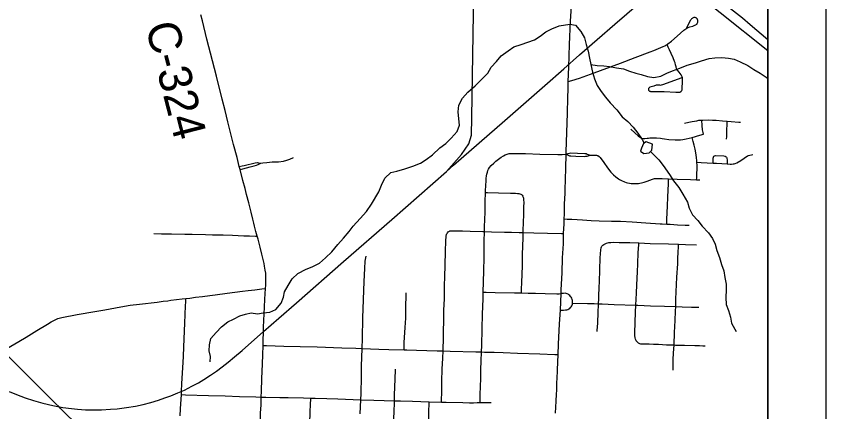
# Model space of a CAD drawing. Extents: x 0 to 34, y 0 to 22.
# Drawn here: x 7.601 to 9, y 14.792 to 15.476 of the extents above; entities that cross this region are included whole.
import ezdxf

# ---------------------------------------------------------------- set-up
doc = ezdxf.new("R2010")
doc.units = 0
for name, color, linetype in [('GM_X_City_Street', 7, 'Continuous'), ('GM_X_Corporation', 7, 'Continuous'), ('GM_X_County_Road', 7, 'Continuous'), ('GM_X_County_Road_Text', 7, 'Continuous'), ('GM_X_Minor_Lake', 7, 'Continuous'), ('GM_X_Minor_River', 7, 'Continuous'), ('GM_X_Rail_Line', 7, 'Continuous'), ('GM_X_State_Route', 7, 'Continuous'), ('SH_Data', 7, 'Continuous')]:
    doc.layers.add(name, color=color, linetype=linetype)

msp = doc.modelspace()

# ---------------------------------------------------------------- linework, layer by layer
at = {"layer": 'GM_X_City_Street'}
for points in [[(8.5552, 15.3632), (8.5614, 15.365), (8.5747, 15.3691), (8.5934, 15.3756), (8.6455, 15.395), (8.6704, 15.4046), (8.6965, 15.4144), (8.7027, 15.4167), (8.7152, 15.4219), (8.7191, 15.4236), (8.7219, 15.425), (8.7239, 15.426), (8.7258, 15.4273), (8.7269, 15.4281), (8.7333, 15.433), (8.7432, 15.4415), (8.755, 15.4517), (8.7602, 15.4552), (8.7625, 15.4564), (8.765, 15.4573), (8.7701, 15.459), (8.7737, 15.4603), (8.7752, 15.461), (8.7762, 15.4617), (8.777, 15.4623), (8.7775, 15.463), (8.778, 15.4638), (8.7784, 15.4646), (8.7787, 15.4655), (8.779, 15.4667), (8.779, 15.468), (8.7789, 15.4689), (8.7786, 15.4698), (8.7781, 15.4709), (8.7774, 15.4719), (8.7767, 15.4727), (8.7761, 15.4731), (8.7754, 15.4734), (8.7744, 15.4737), (8.7732, 15.4738), (8.7718, 15.4737), (8.7708, 15.4733), (8.7698, 15.4728), (8.769, 15.4721), (8.768, 15.4714), (8.7672, 15.4704), (8.7662, 15.4689), (8.7624, 15.4616), (8.7595, 15.4555)], [(8.7511, 15.3695), (8.718, 15.3571), (8.7156, 15.3565), (8.7144, 15.3564), (8.7131, 15.3565), (8.71, 15.3569), (8.708, 15.3567), (8.7069, 15.3565), (8.7027, 15.3553), (8.6962, 15.3532), (8.6952, 15.3526), (8.6947, 15.3521), (8.6939, 15.3512), (8.6935, 15.35), (8.6935, 15.3494), (8.6938, 15.3481), (8.6943, 15.3473), (8.695, 15.3468), (8.6957, 15.3464), (8.6964, 15.3462), (8.6972, 15.3461), (8.6985, 15.346), (8.7205, 15.3457), (8.741, 15.3448), (8.747, 15.3446), (8.7484, 15.3447), (8.7498, 15.3456), (8.7504, 15.3461), (8.7509, 15.3468), (8.7513, 15.3477), (8.7517, 15.3492), (8.7519, 15.3508), (8.7527, 15.3632), (8.7527, 15.3675), (8.7525, 15.3692), (8.752, 15.3711), (8.7515, 15.3725), (8.7502, 15.3744), (8.7467, 15.3794), (8.744, 15.3828), (8.7429, 15.3844), (8.7423, 15.3858), (8.7414, 15.3886), (8.7405, 15.3921), (8.7397, 15.3951), (8.7386, 15.3978), (8.7362, 15.4039), (8.7328, 15.4117), (8.7301, 15.4178), (8.7279, 15.4227), (8.7258, 15.4273)], [(8.7558, 15.2913), (8.7634, 15.2927), (8.7692, 15.2938), (8.7771, 15.2954), (8.7804, 15.296), (8.7838, 15.2964), (8.7858, 15.2965), (8.7874, 15.2965), (8.7978, 15.2966), (8.8042, 15.2963), (8.8108, 15.296), (8.8216, 15.295), (8.8298, 15.2943), (8.8364, 15.2938), (8.8498, 15.2929), (8.8529, 15.2927)], [(8.7889, 15.2718), (8.7881, 15.2747), (8.7875, 15.2771), (8.7871, 15.2794), (8.7869, 15.2813), (8.7865, 15.2852), (8.7862, 15.2887), (8.7859, 15.2946), (8.7858, 15.2965)], [(8.8286, 15.2636), (8.8288, 15.2682), (8.829, 15.2734), (8.8291, 15.2801), (8.8296, 15.2881), (8.8297, 15.2919), (8.8298, 15.2943)], [(8.6633, 15.2809), (8.6701, 15.2743), (8.6759, 15.2691), (8.6783, 15.2672), (8.6799, 15.2661), (8.6817, 15.2652), (8.6834, 15.2646), (8.6847, 15.2644), (8.6862, 15.2644), (8.6876, 15.2644), (8.6916, 15.2649), (8.6937, 15.2652), (8.6962, 15.2656), (8.6993, 15.2658), (8.7029, 15.2659), (8.7075, 15.2657), (8.7142, 15.2652), (8.7173, 15.2648), (8.7214, 15.2643), (8.7288, 15.2629)], [(8.7288, 15.2629), (8.74, 15.2623), (8.7433, 15.2622), (8.7463, 15.2622), (8.7491, 15.2624), (8.753, 15.2627), (8.7588, 15.2639), (8.7691, 15.2666), (8.7824, 15.2701), (8.7889, 15.2718)], [(8.7769, 15.1931), (8.777, 15.1965), (8.7772, 15.2035), (8.7775, 15.2123), (8.7775, 15.2181), (8.7773, 15.2235), (8.7772, 15.2267), (8.7768, 15.2311), (8.7761, 15.2361), (8.7743, 15.2459), (8.7725, 15.2532), (8.771, 15.2593), (8.7691, 15.2666)], [(8.0239, 15.2218), (8.0275, 15.2224), (8.0343, 15.2234), (8.0436, 15.2241), (8.0547, 15.2245), (8.0632, 15.2256), (8.0692, 15.227), (8.0743, 15.2288), (8.0803, 15.2317)], [(8.422, 15.2181), (8.4263, 15.222), (8.4302, 15.2256), (8.4346, 15.2291), (8.4393, 15.2325), (8.443, 15.2347), (8.4462, 15.2362), (8.4498, 15.2376), (8.4532, 15.2384), (8.456, 15.2387), (8.4597, 15.2389), (8.4672, 15.2389), (8.4802, 15.2384), (8.4815, 15.2384), (8.5059, 15.2377), (8.5368, 15.237), (8.5447, 15.237), (8.5515, 15.2374)], [(8.5515, 15.2374), (8.5549, 15.2388), (8.557, 15.2394), (8.5593, 15.2396), (8.5712, 15.2393), (8.5838, 15.2387), (8.586, 15.2384), (8.588, 15.2378), (8.5932, 15.2359)], [(8.5515, 15.2374), (8.5549, 15.2357), (8.5573, 15.2349), (8.5595, 15.2344), (8.568, 15.234), (8.5824, 15.2336), (8.5851, 15.2339), (8.5875, 15.2343), (8.5932, 15.2359)], [(8.5932, 15.2359), (8.5988, 15.236), (8.6023, 15.2359), (8.604, 15.2357), (8.6052, 15.2354), (8.6063, 15.235), (8.6082, 15.2337), (8.6102, 15.2315), (8.6166, 15.2232), (8.6231, 15.2141), (8.6287, 15.2066), (8.633, 15.202), (8.6372, 15.1982), (8.6418, 15.1949), (8.6437, 15.1937), (8.6468, 15.1921), (8.652, 15.1899), (8.655, 15.1888), (8.6577, 15.1881), (8.6609, 15.1875), (8.6637, 15.1871), (8.6671, 15.1868), (8.67, 15.1867), (8.6733, 15.1867), (8.6762, 15.187), (8.6785, 15.1873), (8.6814, 15.1878), (8.6838, 15.1884), (8.6862, 15.1891), (8.6915, 15.191), (8.7006, 15.1945), (8.7024, 15.1951), (8.704, 15.1954), (8.7062, 15.1956), (8.7092, 15.1957), (8.7174, 15.1955), (8.7284, 15.1949), (8.7435, 15.1944), (8.7665, 15.1935), (8.7769, 15.1931), (8.7825, 15.1929)], [(8.7773, 15.2235), (8.7848, 15.2231), (8.8055, 15.2221), (8.8114, 15.2217), (8.8298, 15.2208), (8.8349, 15.2205), (8.8372, 15.2205), (8.8397, 15.2207), (8.8415, 15.221), (8.8432, 15.2215), (8.8465, 15.2228), (8.8533, 15.2268), (8.8647, 15.2344), (8.8664, 15.2352), (8.8685, 15.236), (8.8715, 15.2366), (8.8739, 15.2368)], [(8.8055, 15.2221), (8.8055, 15.2275), (8.8055, 15.2306), (8.8058, 15.2325), (8.8067, 15.2341), (8.8077, 15.2348), (8.8095, 15.2352), (8.8239, 15.2345), (8.8263, 15.2341), (8.8279, 15.2332), (8.8287, 15.2322), (8.8292, 15.2311), (8.8294, 15.2267), (8.8298, 15.2208)], [(7.9868, 15.2164), (7.9915, 15.2173), (7.9955, 15.2182), (8.0144, 15.2226), (8.0181, 15.223), (8.0201, 15.2226), (8.0239, 15.2218)], [(7.9882, 15.211), (7.993, 15.2122), (8.0056, 15.2155), (8.0125, 15.2172), (8.0167, 15.2183), (8.0196, 15.2194), (8.0239, 15.2218)], [(8.4027, 14.8081), (8.4028, 14.811), (8.4032, 14.8236), (8.4034, 14.835), (8.404, 14.8512), (8.4043, 14.8655), (8.4048, 14.8796), (8.4053, 14.8957), (8.4056, 14.907), (8.4063, 14.9359), (8.407, 14.9608), (8.4079, 14.9874), (8.4082, 14.9991), (8.409, 15.0351), (8.4098, 15.0598), (8.4099, 15.0864), (8.4103, 15.1036), (8.4106, 15.1131), (8.411, 15.1236), (8.4113, 15.1383), (8.4118, 15.1551), (8.4122, 15.1712), (8.4123, 15.1735), (8.4126, 15.1837), (8.413, 15.1906), (8.4134, 15.1954), (8.4139, 15.1999), (8.4145, 15.2029), (8.4153, 15.2063), (8.4163, 15.2095), (8.4173, 15.2114), (8.4189, 15.2144), (8.422, 15.2181)], [(8.7252, 15.1167), (8.7255, 15.1235), (8.7256, 15.1253), (8.7266, 15.1476), (8.7273, 15.1637), (8.7281, 15.186), (8.7284, 15.1949)], [(8.4122, 15.1712), (8.4157, 15.1712), (8.4346, 15.1705), (8.4552, 15.1701), (8.4641, 15.1699), (8.4672, 15.1698), (8.4696, 15.1696), (8.4714, 15.1692), (8.4731, 15.1684), (8.4741, 15.1676), (8.4755, 15.1664), (8.4765, 15.1649)], [(8.4744, 14.9978), (8.4746, 15.0042), (8.4749, 15.016), (8.4758, 15.0444), (8.4762, 15.0625), (8.4768, 15.0801), (8.477, 15.0913), (8.4773, 15.1023), (8.4774, 15.1057), (8.4782, 15.133), (8.4784, 15.1373), (8.4785, 15.1453), (8.4787, 15.1552), (8.4786, 15.1572), (8.4784, 15.1595), (8.4781, 15.161), (8.4776, 15.1625), (8.4765, 15.1649)], [(8.5482, 15.1255), (8.5532, 15.1253), (8.5614, 15.1251), (8.5797, 15.124), (8.5947, 15.123), (8.6084, 15.1225), (8.63, 15.1219), (8.6454, 15.1215), (8.6655, 15.1204), (8.6892, 15.1188), (8.7138, 15.1172), (8.7173, 15.1171), (8.7252, 15.1167), (8.7309, 15.1164), (8.7439, 15.1156), (8.7573, 15.115), (8.7638, 15.1147)], [(8.3478, 15.1032), (8.3489, 15.1041), (8.3499, 15.1046), (8.3508, 15.1049), (8.3533, 15.1051), (8.3584, 15.1052), (8.3725, 15.1048), (8.3857, 15.1043), (8.4073, 15.1036), (8.4103, 15.1036), (8.4226, 15.1033), (8.4449, 15.103), (8.4573, 15.1027), (8.4702, 15.1024), (8.4773, 15.1023), (8.4958, 15.1018), (8.519, 15.101), (8.5432, 15.1004), (8.5471, 15.1003)], [(7.8391, 15.1004), (7.8522, 15.1), (7.8695, 15.0997), (7.893, 15.0992), (7.8973, 15.0992), (7.9053, 15.0991), (7.9282, 15.0987), (7.9407, 15.0984), (7.9493, 15.0983), (7.9587, 15.098), (7.9752, 15.0974), (7.9948, 15.0966), (8.0046, 15.0963), (8.0147, 15.0961), (8.0178, 15.096)], [(8.336, 14.8091), (8.3366, 14.8295), (8.3368, 14.8451), (8.3373, 14.8658), (8.3383, 14.8852), (8.3388, 14.8975), (8.3391, 14.9023), (8.3394, 14.9168), (8.3397, 14.9322), (8.34, 14.9491), (8.3403, 14.959), (8.3404, 14.9677), (8.3411, 14.9877), (8.3413, 14.9973), (8.3415, 15.0108), (8.342, 15.0255), (8.3426, 15.0457), (8.3432, 15.0696), (8.3437, 15.0878), (8.3441, 15.0953), (8.3443, 15.0968), (8.3447, 15.0983), (8.345, 15.0993), (8.3457, 15.1004), (8.3466, 15.1016), (8.3478, 15.1032)], [(8.605, 14.931), (8.6052, 14.9329), (8.6059, 14.9452), (8.6066, 14.9645), (8.6072, 14.9771), (8.6073, 14.9789), (8.6077, 14.9878), (8.6079, 14.9921), (8.6087, 15.0075), (8.609, 15.0168), (8.6097, 15.0379), (8.6104, 15.0585), (8.6106, 15.0653), (8.6111, 15.0721), (8.612, 15.0757), (8.6126, 15.0773), (8.6133, 15.0784), (8.615, 15.0803), (8.6163, 15.0813), (8.6175, 15.0821), (8.6212, 15.0838)], [(8.6212, 15.0838), (8.6254, 15.0847), (8.6288, 15.0851), (8.6327, 15.0852), (8.6431, 15.0849), (8.6617, 15.0846), (8.6769, 15.0842), (8.6965, 15.0834), (8.7281, 15.0825), (8.7454, 15.0819), (8.7579, 15.0814), (8.7767, 15.0808)], [(8.6749, 14.9127), (8.6735, 14.9138), (8.6724, 14.9152), (8.6717, 14.9165), (8.6711, 14.9179), (8.6705, 14.9204), (8.6702, 14.9242), (8.67, 14.9289), (8.6715, 14.9643), (8.6721, 14.9764), (8.6731, 14.9972), (8.6738, 15.012), (8.6748, 15.0343), (8.6753, 15.0478), (8.6761, 15.0676), (8.6768, 15.0809), (8.6769, 15.0842)], [(8.7361, 14.864), (8.7365, 14.8829), (8.7371, 14.8934), (8.7378, 14.9078), (8.7389, 14.9294), (8.7398, 14.9501), (8.7405, 14.9662), (8.7407, 14.9741), (8.7409, 14.9768), (8.7412, 14.9868), (8.7429, 15.0248), (8.7441, 15.048), (8.7445, 15.0592), (8.7448, 15.0662), (8.7453, 15.079), (8.7454, 15.0819)], [(8.1959, 14.7887), (8.1964, 14.801), (8.1968, 14.8132), (8.1972, 14.8241), (8.1978, 14.8527), (8.1979, 14.8677), (8.1979, 14.8714), (8.1988, 14.9017), (8.1994, 14.9192), (8.2005, 14.9546), (8.2025, 15.0176), (8.2036, 15.0398), (8.2044, 15.0528), (8.2052, 15.0583), (8.2057, 15.0612)], [(7.5855, 14.9017), (7.6058, 14.9139), (7.6185, 14.9215), (7.637, 14.9327), (7.6555, 14.9439), (7.6617, 14.9476), (7.664, 14.949), (7.6689, 14.9515), (7.6736, 14.9534), (7.6805, 14.9552), (7.7069, 14.9602), (7.737, 14.9654), (7.7548, 14.9685), (7.7819, 14.9737), (7.7984, 14.9765), (7.8142, 14.9783), (7.8448, 14.982), (7.8553, 14.9834), (7.8633, 14.9843), (7.8688, 14.985), (7.888, 14.9873), (7.8944, 14.9881), (7.9012, 14.9889), (7.9114, 14.9902), (7.9233, 14.9917), (7.9359, 14.9932), (7.9452, 14.9945), (7.9658, 14.9972), (7.9924, 15.0007), (8.0023, 15.0019), (8.0139, 15.0033), (8.0258, 15.0046), (8.0322, 15.0052)], [(8.2714, 14.8994), (8.2715, 14.9028), (8.2718, 14.9118), (8.2734, 14.9377), (8.2743, 14.9544), (8.2747, 14.9698), (8.2753, 14.9979)], [(8.4082, 14.9991), (8.4133, 14.9989), (8.4291, 14.9986), (8.4622, 14.9981), (8.4744, 14.9978), (8.4857, 14.9975), (8.4987, 14.9972), (8.5154, 14.9967), (8.5354, 14.9962), (8.5392, 14.9963), (8.5428, 14.9965)], [(8.5416, 14.9678), (8.5467, 14.968), (8.5503, 14.9685), (8.5525, 14.9688), (8.5545, 14.9693), (8.5561, 14.9701), (8.5576, 14.9711), (8.559, 14.9726), (8.56, 14.9738), (8.561, 14.9754), (8.5617, 14.9767), (8.5622, 14.9781), (8.5626, 14.9802), (8.5626, 14.9815), (8.5624, 14.9844), (8.5619, 14.9866), (8.5612, 14.9886), (8.56, 14.9905), (8.5592, 14.9915), (8.5577, 14.9933), (8.5562, 14.9946), (8.5549, 14.9955), (8.5534, 14.9962), (8.5513, 14.9968), (8.5496, 14.9971), (8.5466, 14.9969), (8.5428, 14.9965)], [(7.8849, 14.7853), (7.8855, 14.7972), (7.8867, 14.822), (7.887, 14.8273), (7.8878, 14.841), (7.8887, 14.8591), (7.8898, 14.8779), (7.8902, 14.8878), (7.8911, 14.9045), (7.8926, 14.9454), (7.8938, 14.9754), (7.8942, 14.9826), (7.8944, 14.9881)], [(8.5626, 14.9802), (8.5886, 14.9795), (8.5997, 14.9792), (8.6073, 14.9789), (8.6134, 14.9786), (8.6344, 14.9778), (8.6721, 14.9764), (8.6751, 14.9763), (8.6972, 14.9757), (8.7214, 14.975), (8.7407, 14.9741), (8.7521, 14.9739), (8.7678, 14.9733), (8.7805, 14.9729)], [(8.6749, 14.9127), (8.6761, 14.9115), (8.678, 14.9104), (8.6801, 14.91), (8.6869, 14.9096), (8.6951, 14.9095), (8.7025, 14.9093), (8.7111, 14.9089), (8.7246, 14.9083), (8.7378, 14.9078), (8.7404, 14.9077), (8.75, 14.9075), (8.7559, 14.9074), (8.7738, 14.9068), (8.7817, 14.9067), (8.7875, 14.9064), (8.7915, 14.9063)], [(8.0278, 14.907), (8.0336, 14.9068), (8.0637, 14.906), (8.092, 14.9053), (8.1215, 14.9045), (8.1637, 14.903), (8.1879, 14.9021), (8.1988, 14.9017), (8.2276, 14.9006), (8.2453, 14.9001), (8.2714, 14.8994), (8.2763, 14.8993), (8.2931, 14.8988), (8.3106, 14.8982), (8.3285, 14.8977), (8.3388, 14.8975), (8.3513, 14.8972), (8.3954, 14.8958), (8.4053, 14.8957), (8.4103, 14.8956), (8.4271, 14.8951), (8.4426, 14.8946), (8.4674, 14.8936), (8.5058, 14.8925), (8.5318, 14.8916), (8.5378, 14.8914)], [(8.2539, 14.7796), (8.2543, 14.7937), (8.2547, 14.8066), (8.2549, 14.8115), (8.2552, 14.8207), (8.2556, 14.8362), (8.256, 14.8479), (8.2567, 14.8659)], [(7.8867, 14.822), (7.8941, 14.8217), (7.9337, 14.8206), (7.9622, 14.8197), (7.9874, 14.8187), (8.0155, 14.8179), (8.0248, 14.8177)], [(8.0248, 14.8177), (8.0328, 14.8176), (8.0569, 14.8173), (8.071, 14.817), (8.0978, 14.8163), (8.1102, 14.816), (8.118, 14.8158), (8.1381, 14.8152), (8.157, 14.8146), (8.1968, 14.8132), (8.2193, 14.8126), (8.2372, 14.8121), (8.2549, 14.8115), (8.2651, 14.8112), (8.2862, 14.8105), (8.3146, 14.8096), (8.336, 14.8091), (8.3443, 14.8089), (8.3732, 14.8081), (8.3847, 14.808), (8.3914, 14.808), (8.3976, 14.8082), (8.4027, 14.8081), (8.4106, 14.8081), (8.4222, 14.8083)], [(8.1031, 14.6248), (8.1039, 14.6467), (8.1044, 14.6618), (8.1051, 14.6806), (8.1059, 14.7049), (8.1069, 14.7282), (8.1079, 14.7558), (8.1085, 14.771), (8.1093, 14.7935), (8.1098, 14.8039), (8.1102, 14.816)], [(8.3106, 14.6186), (8.3111, 14.6298), (8.3114, 14.6518), (8.312, 14.6723), (8.3124, 14.6853), (8.3125, 14.6914), (8.3125, 14.6931), (8.3128, 14.7076), (8.3132, 14.7299), (8.3138, 14.7467), (8.3143, 14.7734), (8.3145, 14.7902), (8.3146, 14.8096)]]:
    msp.add_lwpolyline(points, dxfattribs=at)
at = {"layer": 'GM_X_Corporation'}
for points in [[(5.0398, 14.1), (8.9, 14.1), (8.9, 17.5277)], [(6.9117, 14.1), (8.9, 14.1), (8.9, 15.416), (8.7354, 15.548)]]:
    msp.add_lwpolyline(points, dxfattribs=at)
at = {"layer": 'GM_X_County_Road'}
for points in [[(7.9403, 15.399), (7.9309, 15.4362), (7.9231, 15.4677), (7.9204, 15.4781)], [(7.9622, 15.3129), (7.9573, 15.3326), (7.9473, 15.3721), (7.9403, 15.399)], [(7.977, 15.2543), (7.9671, 15.2932), (7.9622, 15.3129)], [(7.9882, 15.211), (7.9868, 15.2164), (7.9829, 15.2319), (7.977, 15.2543)], [(7.9968, 15.1781), (7.9932, 15.1918), (7.9882, 15.211)], [(8.0031, 15.1534), (7.9993, 15.1679), (7.9968, 15.1781)], [(8.0103, 15.1252), (8.0073, 15.1371), (8.0031, 15.1534)], [(8.0178, 15.096), (8.0155, 15.104), (8.0132, 15.1129), (8.012, 15.118), (8.0103, 15.1252)], [(8.0322, 15.0052), (8.0327, 15.0114), (8.0329, 15.0187), (8.0328, 15.0271), (8.0324, 15.0321), (8.0318, 15.0372), (8.0306, 15.0437), (8.0295, 15.0486), (8.0257, 15.0649), (8.023, 15.0766), (8.0193, 15.0907), (8.0178, 15.096)], [(8.0278, 14.907), (8.0289, 14.9384), (8.0294, 14.9501), (8.0305, 14.973), (8.0312, 14.9872), (8.0322, 15.0052)], [(7.676, 14.8001), (7.6687, 14.8075), (7.6555, 14.8206), (7.6304, 14.8456), (7.5784, 14.8975)], [(8.0248, 14.8177), (8.0251, 14.8277), (8.026, 14.8492), (8.0268, 14.8754), (8.0273, 14.8907), (8.0278, 14.907)], [(8.0223, 14.7447), (8.0226, 14.7514), (8.0231, 14.7646), (8.0234, 14.7791), (8.0237, 14.7901), (8.0244, 14.8046), (8.0248, 14.8177)], [(7.7402, 14.7358), (7.7233, 14.753), (7.7004, 14.7759), (7.6889, 14.7873), (7.6775, 14.7987), (7.676, 14.8001)]]:
    msp.add_lwpolyline(points, dxfattribs=at)
at = {"layer": 'GM_X_Minor_Lake'}
msp.add_line((8.6852, 15.2562), (8.6815, 15.2478), dxfattribs=at)
msp.add_lwpolyline([(8.6815, 15.2478), (8.6801, 15.2425), (8.6854, 15.2384), (8.6949, 15.2396), (8.6997, 15.2446), (8.7008, 15.2549), (8.6897, 15.2589), (8.6852, 15.2562)], dxfattribs=at)
at = {"layer": 'GM_X_Minor_River'}
for points in [[(7.9365, 14.8784), (7.9372, 14.8879), (7.9348, 14.8977), (7.9351, 14.908), (7.9376, 14.919), (7.9469, 14.9294), (7.9563, 14.9394), (7.9672, 14.9479), (7.977, 14.9525), (7.9875, 14.958), (7.9973, 14.9608), (8.0075, 14.9635), (8.0182, 14.9618), (8.028, 14.9634), (8.0397, 14.9647), (8.0499, 14.969), (8.0589, 14.9801), (8.0629, 14.9904), (8.0647, 14.9999), (8.071, 15.0106), (8.0781, 15.0221), (8.0882, 15.0313), (8.1025, 15.0387), (8.1127, 15.0426), (8.1251, 15.0492), (8.136, 15.0584), (8.1465, 15.0688), (8.1573, 15.0815), (8.1671, 15.0926), (8.1764, 15.1037), (8.1835, 15.1133), (8.1955, 15.1263), (8.2067, 15.1382), (8.2152, 15.1513), (8.2279, 15.1727), (8.2323, 15.1841), (8.2382, 15.1963), (8.2487, 15.2059), (8.2589, 15.2083), (8.2725, 15.2119), (8.2865, 15.217), (8.2997, 15.2221), (8.3094, 15.2283), (8.3203, 15.2364), (8.3335, 15.2483), (8.3436, 15.2557), (8.353, 15.2653), (8.3631, 15.2768), (8.3675, 15.2874), (8.3658, 15.2988), (8.365, 15.3106), (8.366, 15.3224), (8.3723, 15.3342), (8.3816, 15.3449), (8.3944, 15.3557), (8.406, 15.3669), (8.4161, 15.3776), (8.422, 15.3876), (8.4314, 15.3975), (8.4392, 15.4075), (8.4513, 15.416), (8.461, 15.423), (8.4735, 15.4273), (8.4852, 15.4308), (8.4969, 15.4351), (8.5066, 15.4417), (8.5164, 15.449), (8.5266, 15.4541), (8.5394, 15.4592), (8.5579, 15.462), (8.5674, 15.4603), (8.577, 15.4494), (8.5832, 15.4384), (8.586, 15.4271), (8.5895, 15.4153), (8.5915, 15.4036), (8.5943, 15.3922), (8.5967, 15.3793), (8.6006, 15.3676), (8.6053, 15.3559), (8.6122, 15.3457), (8.6196, 15.3359), (8.6276, 15.3262), (8.6391, 15.3142), (8.6483, 15.3021), (8.6579, 15.2939), (8.6675, 15.2841), (8.6752, 15.2739), (8.6825, 15.263), (8.6861, 15.2567)], [(8.5943, 15.3922), (8.6049, 15.3908), (8.6167, 15.3902), (8.6262, 15.3888), (8.6387, 15.387), (8.6504, 15.3849), (8.6607, 15.3812), (8.6717, 15.3776), (8.6812, 15.3754), (8.6919, 15.3717), (8.7032, 15.37), (8.715, 15.3724), (8.7251, 15.3774), (8.7353, 15.3813), (8.7478, 15.386), (8.7606, 15.3911), (8.7749, 15.3951), (8.7855, 15.399), (8.7987, 15.4026), (8.8085, 15.4042), (8.8206, 15.4044), (8.832, 15.4037), (8.8415, 15.4016), (8.8518, 15.3971), (8.8651, 15.3908), (8.8758, 15.3837), (8.8865, 15.3774), (8.8968, 15.3703), (8.9, 15.3683)], [(8.6971, 15.2419), (8.7113, 15.228), (8.719, 15.2179), (8.7301, 15.2021), (8.7371, 15.1915), (8.7463, 15.1802), (8.7532, 15.1682), (8.761, 15.1546), (8.7641, 15.144), (8.7699, 15.1327), (8.7787, 15.1229), (8.7864, 15.1131), (8.7975, 15.1018), (8.8041, 15.092), (8.8087, 15.0822), (8.8119, 15.0712), (8.8162, 15.0588), (8.8201, 15.047), (8.824, 15.0361), (8.8257, 15.0243), (8.8277, 15.013), (8.8278, 15.0031), (8.8272, 14.9898), (8.8281, 14.978), (8.832, 14.9674), (8.8351, 14.9557), (8.8371, 14.9455), (8.8426, 14.9349), (8.8449, 14.9311)]]:
    msp.add_lwpolyline(points, dxfattribs=at)
at = {"layer": 'GM_X_Rail_Line'}
for points in [[(8.5472, 15.3849), (8.5748, 15.4092), (8.6353, 15.4621), (8.6975, 15.5165), (8.7491, 15.5615), (8.8375, 15.6391), (8.9, 15.6939)], [(8.3449, 15.2078), (8.3704, 15.237), (8.3836, 15.2554), (8.3882, 15.2703), (8.3885, 15.301), (8.3928, 15.5534), (8.392, 15.6079)], [(7.5891, 14.8271), (7.602, 14.822), (7.6171, 14.8164), (7.6314, 14.8116), (7.6475, 14.8071), (7.6649, 14.803), (7.6821, 14.7997), (7.6967, 14.7979), (7.7076, 14.7969), (7.7209, 14.7959), (7.7334, 14.7955), (7.7489, 14.7958), (7.7646, 14.7966), (7.7756, 14.7976), (7.792, 14.7996), (7.8073, 14.8023), (7.8206, 14.8052), (7.8342, 14.8086), (7.8473, 14.8125), (7.8584, 14.8164), (7.8686, 14.8201), (7.8809, 14.8252), (7.892, 14.8299), (7.9049, 14.8365), (7.9161, 14.8425), (7.9254, 14.8483), (7.9369, 14.8555), (7.9474, 14.8627), (7.9571, 14.87), (7.9676, 14.8781), (7.9788, 14.8873), (7.9915, 14.8983), (8.0287, 14.9309), (8.0553, 14.9543), (8.0854, 14.9805), (8.1671, 15.052), (8.2503, 15.1247), (8.3449, 15.2078), (8.3568, 15.2183), (8.4455, 15.2958), (8.5145, 15.3561), (8.5472, 15.3849)]]:
    msp.add_lwpolyline(points, dxfattribs=at)
at = {"layer": 'GM_X_State_Route'}
for points in [[(8.7493, 15.562), (8.7759, 15.5399), (8.8029, 15.5171), (8.8251, 15.4982), (8.8356, 15.4894), (8.8559, 15.473), (8.8693, 15.4617), (8.9, 15.4358)], [(8.5482, 15.1255), (8.5485, 15.134), (8.5486, 15.139), (8.5486, 15.1414), (8.5486, 15.1439), (8.5488, 15.1495), (8.5487, 15.1513), (8.5488, 15.1519), (8.5497, 15.1693), (8.5497, 15.1761), (8.5507, 15.2128), (8.5515, 15.2374), (8.5516, 15.2413), (8.5526, 15.2748), (8.5536, 15.3084), (8.5536, 15.3127), (8.5541, 15.33), (8.5544, 15.3362), (8.5548, 15.3492), (8.5552, 15.3632), (8.5559, 15.3877), (8.5572, 15.4268), (8.5592, 15.4672), (8.5628, 15.5286)], [(8.5333, 14.79), (8.5343, 14.8104), (8.5347, 14.8228), (8.5352, 14.8296), (8.5352, 14.8315), (8.5355, 14.8439), (8.5359, 14.8488), (8.5366, 14.865), (8.5378, 14.8914), (8.5385, 14.909), (8.5402, 14.9444), (8.5416, 14.9678), (8.5428, 14.9965), (8.5431, 15.0028), (8.5443, 15.0326), (8.5454, 15.0586), (8.5466, 15.0826), (8.5471, 15.1003), (8.5478, 15.1173), (8.5482, 15.1255)]]:
    msp.add_lwpolyline(points, dxfattribs=at)
at = {"layer": 'SH_Data'}
for p, q in [((9, 21), (9, 14)), ((8.9, 20.9), (8.9, 14.1))]:
    msp.add_line(p, q, dxfattribs=at)

# ---------------------------------------------------------------- texts
at = {"layer": 'GM_X_County_Road_Text'}
msp.add_text('C-324', height=0.05682, rotation=284.4392, dxfattribs=at).set_placement((7.8243, 15.4592))

doc.saveas('drawing.dxf')
